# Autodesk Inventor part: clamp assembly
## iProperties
Shininess: 64.0
Length Units: 11272
Angle Units: 11279
Time Units: 11290
Mass Units: 11286
Length Display Precision: 3
Compacted: True
Part Number: clamp assembly
Document SubType Name: Modeling
Created: 2002-11
Designer: E. MOSS
Density: 0.0
Volumn: 0.0
Area: 0.0
PropertySet Name: Model Information
Control State: 0
Master: False
Checked Out: False
Author: E. MOSS
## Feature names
1. Extrusion1
2. Hole1
3. Hole2
4. Revolution1
